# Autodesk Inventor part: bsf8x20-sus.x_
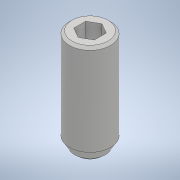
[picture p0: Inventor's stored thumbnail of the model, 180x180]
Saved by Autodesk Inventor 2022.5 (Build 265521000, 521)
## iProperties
Created: 2020-01
Part Number: bsf8x20-sus.x_
Material: 一般
Document SubType Name: Modeling
Designer: ImaoCorp
Density: 1 g/cm^3
Appearance: 既定
Sending System: SOLIDWORKS 2018-2018316
MC: AMD64
MC_MODEL: Intel64 Family 6 Model 60 Stepping 3, GenuineIntel
OS: Windows_NT
FRU: Parasolid Version 30.0, build 310,  6- 8-2018
FORMAT: text
GUISE: transmit
KEY: bsf8x20-sus
FILE: bsf8x20-sus.x_t
DATE: Thu Jan 23 16:48:18 2020
Author: ImaoCorp
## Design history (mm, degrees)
feature "Base1"
node "ソリッド1"
